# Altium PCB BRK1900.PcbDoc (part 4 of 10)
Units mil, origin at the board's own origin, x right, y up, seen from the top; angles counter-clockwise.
Board outline 8858.27 x 5905.51 mil, 10 copper layers (L1-TOP, L2-GND, L3-SIG1, L4-GND, L5-PWR, L6-PWR, L7-GND, L8-SIG2, L9-GND, L10-BOT), stack 48.824 mil thick; 507 components, 607 nets, 2498 pads, 2210 vias.
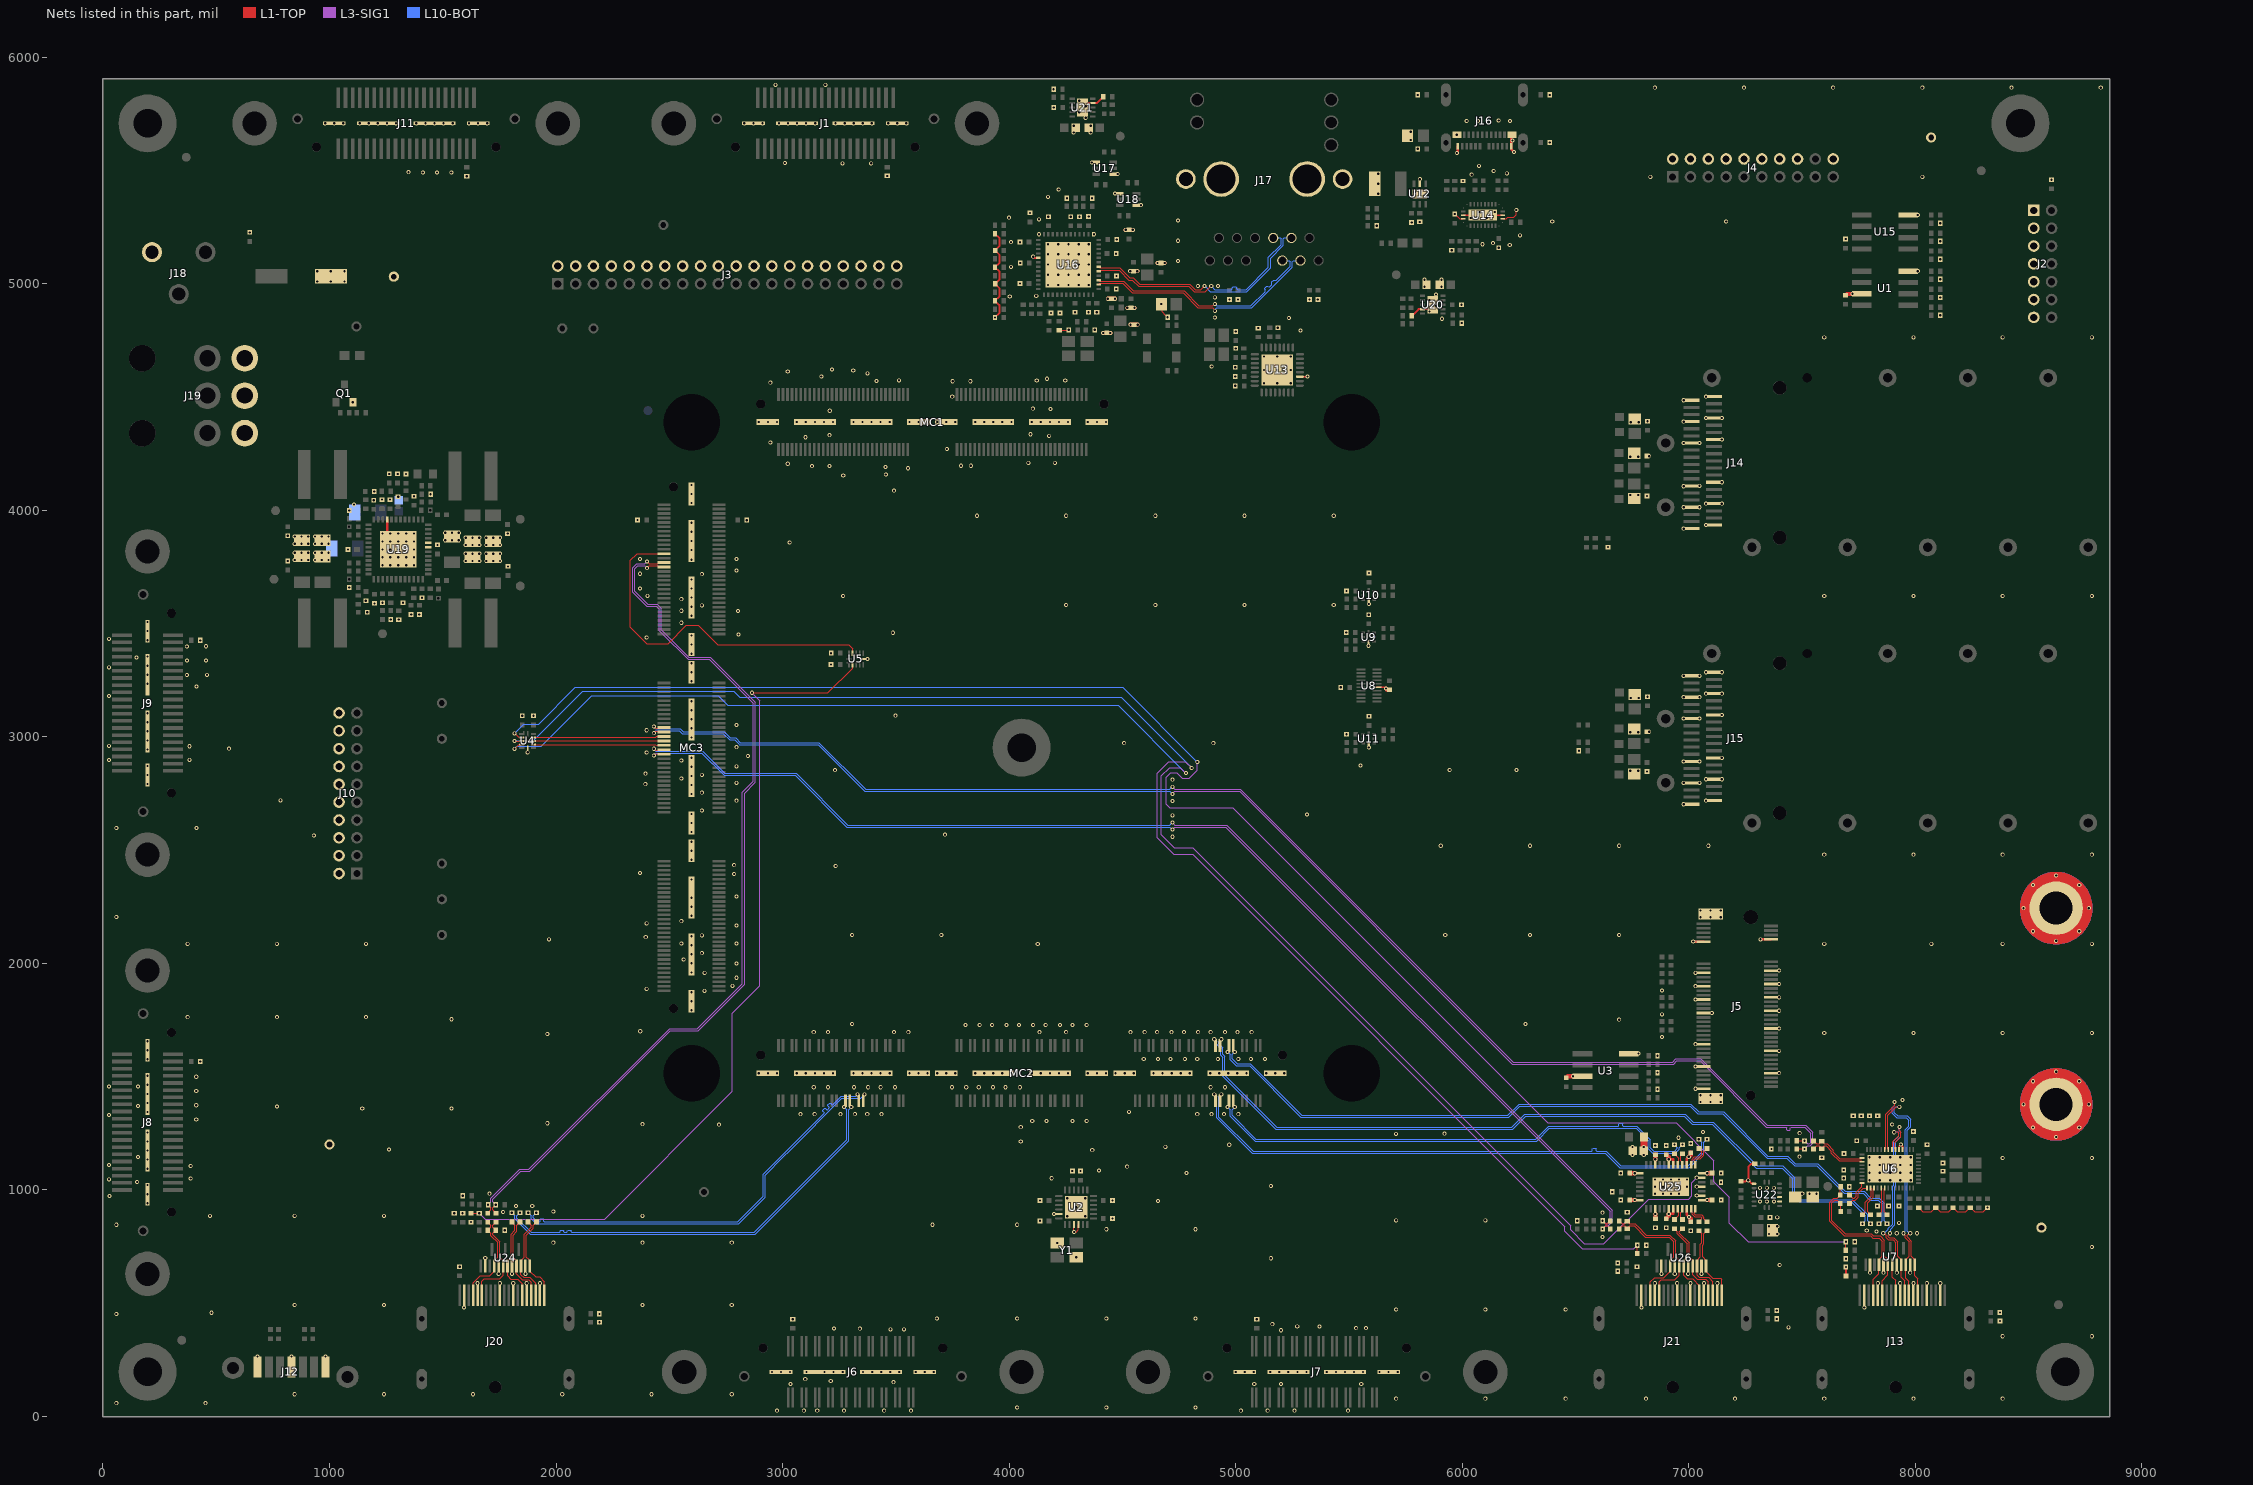
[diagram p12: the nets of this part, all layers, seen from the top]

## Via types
v1: diameter 18, hole 10, L1-TOP to L10-BOT, tented both sides, 2210 vias

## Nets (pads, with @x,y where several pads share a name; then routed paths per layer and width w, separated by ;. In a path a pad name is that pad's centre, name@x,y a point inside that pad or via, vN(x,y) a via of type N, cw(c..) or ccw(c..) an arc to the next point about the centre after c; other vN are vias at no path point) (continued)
DGND: C1.1 C2.1 C3.1 C4.1 C5.1 C6.1 C7.1 C8.1 C9.1 C18.1 C19.1 C20.2 C21.2 C22.1 C23.1 C29.1 C37.1 C38.2 C39.2 C40.1 C41.1 C42.1 C43.1 C44.1 C45.1 C46.1 C47.1 C48.1 C49.1 C50.1 C51.1 C52.1 C53.1 C54.1 C55.1 C56.1 C57.1 C58.1 C59.1 C60.1 C61.1 C62.1 C63.1 C64.1 C65.1 C66.1 C67.1 C68.1 C69.1 C70.1 C71.1 C72.1 C73.1 C74.1 C75.1 C76.1 C77.1 C78.1 C81.1 C82.1 C83.1 C84.1 C85.2 C86.1 C87.2 C88.1 C89.1 C90.1 C91.1 C92.1 C93.1 C94.1 C95.1 C96.2 C97.1 C98.1 C99.1 C100.1 C101.2 C102.1 C103.2 C104.1 C105.1 C106.1 C107.1 C108.1 C109.1 C110.2 C111.2 C112.1 C113.1 C114.1 C115.1 C116.2 C117.2 C119.1 C120.1 C121.1 C123.2 C124.2 C125.2 C127.2 C128.2 C129.1 C130.1 C131.1 C132.1 C134.2 C135.1 C136.2 C137.2 C138.2 C140.2 C141.2 C142.1 C143.1 C144.1 C146.2 C147.2 C148.2 C150.1 C151.1 C152.1 C155.2 C156.1 C157.2 C158.1 C159.1 C160.1 C162.1 C164.1 C165.1 C167.1 C168.1 C169.1 C176.1 C177.1 C183.1 C190.1 C191.1 C192.1 C193.1 C194.1 C195.1 C196.1 C197.1 C198.1 C199.1 C200.1 C201.1 C204.1 C211.1 FB1.2 J1.0 J2.1 J2.3 J2.5 J2.7 J2.9 J2.11 J2.13 J3.2 J3.4 J3.6 J3.8 J3.10 J3.12 J3.14 J3.16 J3.18 J3.20 J3.22 J3.24 J3.26 J3.28 J3.30 J3.32 J3.34 J3.36 J3.38 J3.40 J4.2 J4.4 J4.6 J4.8 J4.10 J4.12 J4.14 J4.16 J4.20 J5.1 J5.8 J5.11 J5.18 J5.21 J5.28 J5.35 J5.36 J5.41 J5.42 J5.47 J5.48 J5.53 J5.54 J5.67 J5.68 J6.0 J7.0 J8.0 J9.0 J10.2 J10.4 J10.6 J10.8 J10.10 J10.12 J10.14 J10.16 J10.18 J10.20 J11.0 J12.1 J12.4 J12.7 J13.2 J13.5 J13.8 J13.11 J13.16 J13.19 J14.1 J14.4 J14.7 J14.13 J14.16 J14.19 J14.20 J14.23 J14.26 J14.32 J14.35 J14.38 J15.1 J15.4 J15.7 J15.13 J15.16 J15.19 J15.20 J15.23 J15.26 J15.32 J15.35 J15.38 J16.A1 J16.A12 J16.B1 J16.B12 J17.S1 J17.S2 J17.T1 J17.T2 J18.2 J19.4 J19.5 J19.6 J20.2 J20.5 J20.8 J20.11 J20.16 J20.19 J21.2 J21.5 J21.8 J21.11 J21.16 J21.19 MC1.0 MC2.0 MC3.0 Q1.2 R1.1 R5.1 R6.1 R7.1 R11.1 R12.1 R13.1 R14.1 R15.1 R16.1 R17.1 R18.1 R19.2 R20.2 R21.2 R22.2 R25.1 R26.1 R27.1 R28.1 R29.1 R35.1 R36.1 R37.1 R38.1 R39.1 R40.1 R47.1 R60.1 R66.1 R70.2 R73.2 R76.1 R77.2 R78.2 R79.2 R83.1 R87.1 R88.1 R89.1 R98.1 R99.1 R100.1 R101.1 R102.1 R103.1 R109.2 R114.1 R115.1 R116.1 R119.1 R123.1 R126.1 R130.1 R131.2 R134.1 R135.1 R142.1 R143.1 R147.1 R150.2 R151.2 R154.1 R155.1 R156.1 R157.1 R159.1 R161.1 R162.1 R163.1 R164.1 R165.1 R166.1 R169.1 R171.1 R175.1 R177.1 SO1.1 SO2.1 TP2.1 TP5.1 TP8.1 TP11.1 U1.4 U1.7 U2.3 U2.4 U2.23 U2.PAD U3.4 U3.7 U4.6 U5.6 U6.13 U6.14 U6.PAD U7.2 U7.5 U7.8 U7.11 U8.15 U9.4 U10.4 U11.4 U12.0 U12.5 U13.0 U13.11 U14.12 U14.13 U14.28 U14.29 U14.PAD U15.4 U16.0 U16.13 U16.29 U17.1 U17.4 U18.1 U18.4 U19.7 U19.8 U19.21 U19.PAD U20.4 U20.PAD U21.4 U21.PAD U22.2 U22.3 U22.9 U24.2 U24.5 U24.8 U24.11 U25.33 U25.35 U25.PAD U26.2 U26.5 U26.8 U26.11 Y1.2 Y1.4 | length 5920.7
  L1-TOP w5: R114.1@4222.06,4795.45 4261.3,4795.45 v1(4262.98,4797.14) ; U2.3@4286.39,847.02 4286.39,815.08 v1(4287.13,814.34) 4296.78,814.34 4306.07,823.63 U2.4@4306.07,847.02 ; v1(4671.82,4910.57) 4675.7,4906.7 4675.7,4876.48 4690.29,4861.89 4692.26,4861.89 4699.6,4854.54 v1(4699.6,4852.57) ; v1(5967.41,5308.4) 5968,5308.4 5975.74,5300.67 5975.74,5300.07 5988.31,5287.5 U14.29@6005.76,5287.5 ; U14.12@6178.99,5287.5 6194.5,5287.5 6201,5294 6227.22,5294 6239.22,5306 v1(6239.22,5326) ; R36.1@8014.77,922.57 8034.09,903.26 8071.46,903.26 R37.1@8090.77,922.57 8110.09,903.26 8147.46,903.26 R38.1@8166.77,922.57 8186.09,903.26 8223.46,903.26 R39.1@8242.77,922.57 8262.09,903.26 8299.46,903.26 v1(8318.77,922.57)
  L1-TOP w7: U13.11@5283.35,4590.53 5317.07,4590.53 v1(5317.41,4590.87) ; v1(7693.84,660) 7694.45,659.39 C29.1@7694.45,621 ; U6.14@7928.5,1179.26 7928.5,1193.25 v1(7936.34,1201.08) 7944.25,1193.17 U6.13@7944.25,1179.26
  L1-TOP w7.5: U8.15@5623.43,3219.13 5657.74,3219.13 v1(5663.37,3213.5) ; U14.28@6005.76,5303.24 6091,5303.24 U14.PAD@6091.59,5303.83 6092.18,5303.24 U14.13@6178.99,5303.24
  L1-TOP w8: v1(3937.8,4851.42) 3957,4870.62 3957,4906.22 R98.1@3937.8,4925.42 3958,4945.62 3958,4979.62 R103.1@3937.94,4999.68 3958,5019.73 3958,5053.12 R102.1@3937.7,5073.41 3958,5093.71 3958,5127.3 R101.1@3937.89,5147.41 3958,5167.53 3958,5201.22 R100.1@3937.8,5221.42
  L1-TOP w9: v1(4106.06,5120.14) 4111.39,5114.81 U16.29@4128.04,5114.81 ; U21.PAD@4323.94,5778.23 4343.62,5797.91 U21.4@4369.21,5797.91 4386.46,5797.91 4415,5826.46 R143.1@4416.31,5826.46 ; R142.1@5777.62,4859.77 5778.94,4859.77 5807.48,4888.31 U20.4@5824.72,4888.31 5850.31,4888.31 U20.PAD@5870,4908 ; C177.1@7235,1036.59 7250.11,1036.59 7256,1042.48 v1(7263,1042.48) ; U22.9@7285.94,1027.69 7278.79,1027.69 7264,1042.48 v1(7263,1042.48) ; R147.1@7291,1114.2 7274.72,1114.2 7263,1102.48 v1(7263,1042.48)
  L1-TOP w11: C157.2@1158.5,3601.56 C157.2@1161.58,3601.56 ; C146.2@1197.7,3589.45 v1(1198.29,3589.45) ; U19.21@1254.37,3959.53 1254.37,3876.85 v1(1303.58,3827.64) ; C156.1@1269.81,3518.08 v1(1270.4,3518.08) ; R134.1@1304.81,3517.87 v1(1305.4,3517.87) ; C124.2@1324.41,3591.92 v1(1325,3591.92) ; C125.2@1359.99,3540.48 v1(1360.58,3540.48) ; v1(5976.48,5578.02) 5980.31,5581.85 J16.A12@5980.31,5607.09 ; J16.A1@6216.17,5602.2 6216.17,5594.75 v1(6228.82,5582.1) ; J16.A1@6216.54,5607.09 6216.54,5654.33 J16.B12@6220.47,5658.27 ; v1(7019.94,2096.46) J5.67@7065.94,2096.46 ; v1(7317.19,2106.3) J5.68@7363.19,2106.3
  L1-TOP w18: v1(4415.25,4783.49) C96.2@4431,4783.49 v1(4446.75,4783.49) ; v1(4435.86,4934.37) C85.2@4451.61,4934.37 v1(4467.35,4934.37) ; v1(4514.65,5238.47) v1(4546.14,5238.47) C101.2@4530,5238.47 ; v1(4521.86,4894.21) C86.1@4537.61,4894.21 v1(4553.35,4894.21) ; v1(4534.27,5055.99) C103.2@4550.02,5055.99 v1(4565.76,5055.99) ; v1(4536.25,4819.65) C95.1@4552,4819.65 v1(4567.75,4819.65) ; v1(4655.27,5092.15) C102.1@4671.02,5092.15 v1(4686.76,5092.15) ; v1(5663.37,3213.5) 5669.29,3207.58 C56.1@5678.63,3207.58 ; C9.1@6459.6,1496.23 6460.19,1496.23 6466.11,1502.15 v1(6489.24,1502.15) U3.7@6531.24,1502.15 ; C2.1@7693,4950.08 7693.59,4950.08 7699.51,4956 v1(7722.64,4956) U1.7@7764.64,4956 ; C94.1@7693,5198.08 C94.1@7693.59,5198.08
  L1-TOP w60: 8752.05,1377.95 ccw(c8622.05,1377.95) 8752.05,1377.95 ; 8752.05,2244.09 ccw(c8622.05,2244.09) 8752.05,2244.09
  L10-BOT w7: v1@1233.58,3754.66 v1(1233.58,3757.64)
  L10-BOT w60: 8752.05,1377.95 ccw(c8622.05,1377.95) 8752.05,1377.95 ; 8752.05,2244.09 ccw(c8622.05,2244.09) 8752.05,2244.09
  other v1: 2975.93,25.8 3094.04,25.8 3153.1,25.8 3271.21,25.8 3448.38,25.8 3566.49,25.8 5023.18,25.8 5141.29,25.8 5259.4,25.8 5495.62,25.8 4035.43,39.37 4429.13,39.37 4822.83,39.37 59.06,59.06 452.76,59.06 5708.66,78.74 6102.36,78.74 6456.69,78.74 6811.02,78.74 7204.72,78.74 7598.43,78.74 7992.13,78.74 8385.83,78.74 846.46,98.43 1240.16,98.43 1633.86,98.43 2027.56,98.43 2421.26,98.43 2775.59,98.43 3034.99,143.91 5082.23,143.91 5200.34,143.91 5554.67,143.91 3489.31,151.62 3212.85,156.8 3100,165 2952.88,196.85 2992.88,196.85 3032.88,196.85 3105.38,196.85 3185.38,196.85 3225.38,196.85 3265.38,196.85 3355.38,196.85 3395.38,196.85 3435.38,196.85 3475.38,196.85 3515.38,196.85 3587.88,196.85 3627.88,196.85 3667.88,196.85 5000.13,196.85 5040.13,196.85 5080.13,196.85 5152.63,196.85 5192.63,196.85 5232.63,196.85 5272.63,196.85 5312.63,196.85 5402.63,196.85 5442.63,196.85 5482.63,196.85 5522.63,196.85 5562.63,196.85 5635.13,196.85 5675.13,196.85 5715.13,196.85 682.48,265.5 832.48,265.5 982.48,265.5 8385.83,354.33 8779.53,354.33 5200,381 3477,385 3536,385 3226.85,388.35 3341,388 5532,390 5576,390 7440.94,393.7 5370,397 5272,398 5162.11,407.59 2192.08,416 8374.08,422 3045,429.69 5093,429.69 7388.69,431 3681.1,433.07 4035.43,433.07 4429.13,433.07 4822.83,433.07 59.06,452.76 2191.69,453 479.55,457.99 8373.69,459 7389.08,468 5708.66,472.44 6102.36,472.44 6456.69,472.44 1594.28,480.95 6791.13,480.95 7775.38,480.95 846.46,492.13 1240.16,492.13 2381.89,492.13 2775.59,492.13 1653.75,588.34 1752.18,588.34 1811.23,588.34 1870.29,588.34 1929.34,588.34 6850.6,588.34 6949.03,588.34 7008.08,588.34 7067.14,588.34 7126.19,588.34 7834.85,588.34 7933.28,588.34 7992.33,588.34 8051.39,588.34 8110.44,588.34 1746.72,629.96 1805.78,629.96 1864.83,629.96 6879.4,629.81 6938.46,629.81 6997.51,629.81 7056.57,629.81 7800.59,634.96 7859.65,634.96 7918.7,634.96 7977.76,634.96 6686.84,642 1574.53,661.08 6771.53,661.08 7401.57,669.29 6686.84,678 7693.84,697 5155.54,698.66 1687.67,700.04 4295.96,703.29 8779.53,748.03 6813.21,756 4212.5,766.28 1988.19,767.72 2381.89,767.72 2775.59,767.72 7733.21,771 6619.69,792 7354,805.32 7390.84,805.32 7918.44,809 8007.72,809 7828.94,816.27 7009,819.92 7786,821 1773.9,822 4429.13,826.77 4822.83,826.77 6852.83,833.36 6900.83,833.36 7354,839.48 7390.84,839.48 59.06,846.46 3661.42,846.46 4035.43,846.46 7928,855 1624.53,858.31 4136.15,863.79 6508.31,864 5708.66,866.14 6102.36,866.14 4456.31,873.79 7359.08,879.48 7390.84,879.19 4256.23,883.79 4336.23,883.79 472.44,885.83 846.46,885.83 1240.16,885.83 2381.89,885.83 4198.46,894.26 1550.53,897.69 1587.53,897.69 6619.68,900 6729,901.37 1766.53,903 1988.19,905.51 4296.23,923.79 1823.09,929.08 1895.09,929.08 7832.77,929.18 7882.77,929.18 7928.77,929.18 196.85,941.71 7315,949.48 7345,949.48 7377,949.48 4657.81,951.76 4136.15,953.79 4456.31,953.79 6699.75,955.44 7142.91,955.44 4256.23,963.79 4336.23,963.79 28.71,973.62 1588.84,975 7035.43,975.51 196.85,981.71 6850.75,983.39 6886.18,983.39 6921.61,983.39 6957.05,983.39 1706.53,984 7501.18,983.94 7533.52,983.94 7564.17,983.94 6662.2,991.59 7315,1009.48 7345,1009.48 7376,1009.48 7709.69,1014 6850.75,1014.88 6886.18,1014.88 6921.61,1014.88 6957.05,1014.88 6992.48,1014.88 7035.43,1014.88 5155.48,1017.28 196.85,1021.71 7142.51,1034.44 151,1035 7798.58,1042.84 7843.86,1042.84 7889.13,1042.84 7934.41,1042.84 7979.68,1042.84 6850.75,1046.38 6886.18,1046.38 6921.61,1046.38 6957.05,1046.38 6992.48,1046.38 27.05,1047.26 387.02,1050.31 4188,1051.75 7684.69,1052.26 6699.75,1074.44 7142.91,1074.44 4782.62,1074.91 7798.58,1076.7 7843.86,1076.7 7889.13,1076.7 7934.41,1076.7 7979.68,1076.7 8121.77,1083.42 4279.23,1083.87 4315.23,1083.87 4397,1085.75 7684.69,1088.26 196.85,1094.21 4521.04,1102.89 387.2,1106.15 27.05,1110.26 7798.58,1110.56 7843.86,1110.56 7889.13,1110.56 7934.41,1110.56 7979.68,1110.56 8121.77,1119.1 196.85,1134.21 8385.83,1141.73 8779.53,1141.73 7587,1143.31 7798.58,1144.42 7843.86,1144.42 7889.13,1144.42 7934.41,1144.42 7979.68,1144.42 155,1146 7489,1147 6752.22,1154.72 7685.69,1160.26 196.85,1174.21 4367.19,1175.79 1263.13,1178.3 7365.31,1181 6752.22,1190.16 4689.61,1190.54 6852.83,1196.52 6900.83,1196.52 4971.95,1199.76 8052.77,1200.34 7009,1205.08 196.85,1214.21 4051.5,1214.25 7741.69,1217.26 6954.83,1230.52 8622.05,1233.61 5707.77,1247.95 5921.49,1248.55 7490,1251 196.85,1254.21 7063,1256 7991.77,1258.42 8519.98,1275.89 8724.11,1275.89 4051.5,1277.24 2719.41,1288.53 7898.33,1289.21 2381.35,1290.51 1961.7,1294.62 4102.36,1304.6 4165.35,1304.6 4279.53,1304.6 4342.52,1304.6 412.01,1311.07 7725.77,1326.94 7761.77,1326.94 7797.77,1326.94 7833.77,1326.94 27.05,1330.76 3078.74,1334.6 3141.73,1334.6 3255.91,1334.6 3318.9,1334.6 3374.02,1334.6 3437.01,1334.6 4830.71,1334.6 4893.7,1334.6 4948.82,1334.6 5011.81,1334.6 196.85,1344.21 4529.39,1344.86 1144.64,1359.87 1538.35,1359.87 767.84,1369.07 155,1371 412.01,1374.07 8477.71,1377.95 8766.39,1377.95 196.85,1384.21 7052,1388.09 7096.46,1388.09 7140.91,1388.09 7943.6,1397.68 7052,1418 7096.46,1418 7140.91,1418 196.85,1424.21 412.01,1437.07 6862.28,1444.15 7029.94,1446.85 3137.8,1453.59 3200.79,1453.59 3314.96,1453.59 3377.95,1453.59 3433.07,1453.59 3496.06,1453.59 3748.03,1453.59 3811.02,1453.59 3866.14,1453.59 3929.13,1453.59 3984.25,1453.59 4047.24,1453.59 4889.76,1453.59 4952.76,1453.59 27.05,1456.76 154.35,1456.76 196.85,1464.21 8519.98,1480.02 8724.11,1480.02 412.01,1500.07 196.85,1504.21 2895.24,1515.75 2935.24,1515.75 2975.24,1515.75 3062.72,1515.75 3102.72,1515.75 3142.72,1515.75 3182.72,1515.75 3222.72,1515.75 3312.72,1515.75 3352.72,1515.75 3392.72,1515.75 3432.72,1515.75 3472.72,1515.75 3560.2,1515.75 3600.2,1515.75 3640.2,1515.75 3682.64,1515.75 3722.64,1515.75 3762.64,1515.75 3850.12,1515.75 3890.12,1515.75 3930.12,1515.75 3970.12,1515.75 4010.12,1515.75 4100.12,1515.75 4140.12,1515.75 4180.12,1515.75 4220.12,1515.75 4260.12,1515.75 4347.6,1515.75 4387.6,1515.75 4427.6,1515.75 4470.04,1515.75 4510.04,1515.75 4550.04,1515.75 4637.52,1515.75 4677.52,1515.75 4717.52,1515.75 4757.52,1515.75 4797.52,1515.75 4887.52,1515.75 4927.52,1515.75 4967.52,1515.75 5007.52,1515.75 5047.52,1515.75 5135,1515.75 5175,1515.75 5215,1515.75 7399.19,1515.75 6862.28,1518.15 8622.05,1522.29 7029.94,1545.28 429.69,1567 196.85,1576.71 4594.49,1577.91 4657.48,1577.91 4712.6,1577.91 4775.59,1577.91 4830.71,1577.91 4921.26,1577.91 5011.81,1577.91 5066.93,1577.91 5129.92,1577.91 6862.28,1592.15 6777.96,1602.15 7399.19,1614.17 196.85,1616.71 7029.94,1643.7 196.85,1656.71 6881.92,1675.51 1961.7,1688.32 7598.43,1692.91 7992.13,1692.91 8385.83,1692.91 8779.53,1692.91 3137.8,1696.9 3200.79,1696.9 3492.13,1696.9 3555.12,1696.9 4133.86,1696.9 4251.97,1696.9 4535.43,1696.9 4598.42,1696.9 4653.54,1696.9 4716.54,1696.9 4771.65,1696.9 4834.65,1696.9 4889.76,1696.9 4952.76,1696.9 5007.87,1696.9 5070.87,1696.9 2371.64,1700.6 7399.19,1712.6 3807.09,1728.39 3870.08,1728.39 3925.2,1728.39 3988.19,1728.39 4043.31,1728.39 4106.3,1728.39 4161.42,1728.39 4224.41,1728.39 4279.53,1728.39 4342.52,1728.39 3307.09,1732.28 6279.53,1732.28 6692.91,1751.97 1538.35,1753.57 374.14,1762.77 767.84,1762.77 1161.54,1762.77 6881.92,1775.5 7101.94,1781.5 7399.19,1791.34 2598.42,1792.87 2598.42,1832.87 7029.94,1840.55 7399.19,1850.39 2598.42,1872.87 2655.37,1879.15 6881.92,1881 2400.28,1887.8 7029.94,1899.61 2778.67,1901.21 7399.19,1909.45 2796.57,1936.88 2656.13,1958.52 7029.94,1958.66 2598.42,1960.35 7399.19,1968.5 2598.42,2000.35 2796.57,2000.03 2563.64,2017.68 2598.42,2040.35 2643.58,2045.28 2598.42,2080.35 4126.55,2085.79 374.02,2086.61 767.72,2086.61 1161.42,2086.61 7598.43,2086.61 8070.87,2086.61 8385.83,2086.61 8779.53,2086.61 2553.27,2088.48 2796.57,2088.58 8622.05,2099.76 1968.5,2106.3 2396,2116 2598.42,2120.35 2643.58,2124.02 3307.09,2125.98 3700.79,2125.98 5925.2,2125.98 6299.21,2125.98 6692.91,2125.98 8519.98,2142.03 8724.11,2142.03 2796.57,2167.32 2400.28,2177.2 2553.27,2186.91 7052,2204.05 7096.46,2204.05 7140.91,2204.05 59.06,2204.72 2598.42,2210.35 7052,2233.96 7096.46,2233.96 7140.91,2233.96 8477.71,2244.09 8766.39,2244.09 2598.42,2250.35 2598.42,2290.35 2796.44,2295.95 8519.98,2346.16 8724.11,2346.16 2598.42,2370.35 8622.05,2388.43 2786.57,2394.67 2370.28,2399.61 3234.54,2430.29 2786.57,2434.04 2598.42,2457.83 7598.43,2480.32 7992.13,2480.32 8385.83,2480.32 8779.53,2480.32 2598.42,2497.83 5905.51,2519.68 6299.21,2519.68 6692.91,2519.68 7086.61,2519.68 2598.42,2537.83 4721,2559.37 931,2565 3716.72,2568.55 2598.42,2580.28 59.06,2598.43 413.39,2598.43 2598.42,2620.28 4721,2653.86 5314.96,2657.48 2598.42,2660.28 2643.58,2675.2 6977.61,2702.92 4721,2716.85 2796.57,2718.5 7076.43,2718.67 784,2720 2598.42,2747.76 2643.58,2753.94 2598.42,2787.76 2394.28,2791.31 196.85,2792.11 2796.57,2797.24 6977.61,2797.41 7047.61,2797.41 4721,2811.34 7076.43,2813.16 7146.43,2813.16 2553.27,2816.93 2598.42,2827.76 196.85,2832.11 2643.58,2832.68 2394.85,2837.88 6815.79,2847.17 6741.79,2851.24 6777.79,2851.24 3231.05,2853.21 5944.88,2854.33 6240.16,2854.33 2598.42,2867.76 2796.85,2870.17 196.85,2872.11 5551.18,2874.02 6977.61,2891.9 7047.61,2891.9 2553.27,2895.67 27.05,2897.66 381.68,2899.01 2598.42,2907.76 7146.43,2907.65 2846.57,2915.35 2400.28,2931.1 1875,2932 6515.31,2938.7 196.85,2944.61 556,2948 5588,2953.36 2796.57,2954.72 381.62,2958.8 27.05,2960.66 4507.87,2972.44 4901.57,2972.44 196.85,2984.61 2598.42,2997.76 5489.38,3011.65 6741.79,3020.24 6777.79,3020.24 6825.64,3022.77 196.85,3024.61 2400.28,3029.53 2598.42,3037.76 2796.57,3053.15 196.85,3064.61 2598.42,3077.76 6977.61,3080.87 7047.61,3080.87 5588.46,3090.72 1851,3093.08 1901,3093.08 3498.28,3093.72 7146.43,3096.62 196.85,3104.61 2598.42,3117.76 2598.42,3157.76 6744,3172.18 6780,3172.18 6977.61,3175.36 7047.61,3175.36 6817.81,3177.26 27.05,3181.16 7076.43,3191.11 7146.43,3191.11 5463.92,3219 413.36,3223.05 196.85,3234.61 2598.42,3245.24 6977.61,3269.85 7047.61,3269.85 370.31,3273.85 459.14,3274 196.85,3274.61 2598.42,3285.24 7076.43,3285.6 7146.43,3285.6 27.05,3307.16 196.85,3314.61 3214.09,3320.17 2598.42,3325.24 370.6,3337.19 454.75,3336.87 3375,3344 147.79,3351.01 196.85,3354.61 2598.42,3367.68 3214.3,3369.62 370.48,3398.93 455.2,3400.18 5587,3402.36 2598.42,3407.68 429.69,3426 196.85,3427.11 27.05,3433.16 2400.28,3438.98 2598.42,3447.68 2805.07,3452.56 3486.66,3459.72 5488.38,3460.65 196.85,3467.11 2553.27,3503.94 196.85,3507.11 2598.42,3535.16 5587.46,3539.72 1396.66,3540.56 1166.24,3550.66 2802.87,3556.33 2553.27,3557.09 2598.42,3575.16 2643.58,3580.71 4251.97,3582.68 4645.67,3582.68 5039.37,3582.68 5433.07,3582.68 5588,3586.36 1234.29,3591.84 1160.04,3601.56 2553.27,3608.27 1408.58,3613.95 2598.42,3615.16 3267.72,3622.05 7598.43,3622.05 7992.13,3622.05 8385.83,3622.05 8779.53,3622.05 2404,3623 5489.38,3644.65 2598.42,3655.16 2370.28,3655.51 1087.21,3659.64 2598.42,3695.16 2643.58,3718.5 2370.28,3720.47 5588.46,3723.72 2796.57,3734.25 1787.58,3752.72 1268.58,3757.64 1303.58,3757.64 1338.58,3757.64 1373.58,3757.64 815.58,3776.8 1601.58,3776.64 1631.58,3776.64 1661.58,3776.64 1692.58,3776.64 1722.58,3776.64 1752.58,3776.64 846.18,3780.64 876.18,3780.64 905.88,3780.64 935.58,3780.64 965.58,3780.64 995.58,3780.64 2597.63,3781.99 2370.28,3785.43 2796.57,3785.43 1233.58,3792.64 1268.58,3792.64 1303.58,3792.64 1338.58,3792.64 1373.58,3792.64 1601.58,3808.81 1631.58,3808.81 1661.58,3808.81 1692.58,3808.81 1722.58,3808.81 1752.58,3808.81 846.18,3812.81 876.18,3812.81 905.88,3812.81 935.58,3812.81 965.58,3812.81 995.58,3812.81 2598.42,3825.16 1081.5,3827.64 1233.58,3827.64 1268.58,3827.64 1338.58,3827.64 1373.58,3827.64 6644,3838.02 1601.58,3847.46 1631.58,3847.46 1661.58,3847.46 1692.58,3847.46 1722.58,3847.46 1752.58,3847.46 1476.58,3847.72 846.18,3852.46 876.18,3852.46 905.88,3852.46 935.58,3852.46 965.58,3852.46 995.58,3852.46 3031.5,3858.27 1233.58,3862.64 1268.58,3862.64 1303.58,3862.64 1338.58,3862.64 1373.58,3862.64 2598.42,3865.16 1510.58,3868.64 1540.58,3868.64 1570.58,3868.64 1601.58,3879.64 1631.58,3879.64 1661.58,3879.64 1692.58,3879.64 1722.58,3879.64 1752.58,3879.64 846.18,3884.64 876.18,3884.64 905.88,3884.64 935.58,3884.64 965.58,3884.64 995.58,3884.64 815.58,3887.56 1233.58,3897.64 1268.58,3897.64 1303.58,3897.64 1338.58,3897.64 1373.58,3897.64 1786.58,3897.56 1510.58,3900.81 1540.58,3900.81 1570.58,3900.81 2598.42,3905.16 6977.61,3919.39 7076.43,3935.14 2598.42,3945.16 2842.16,3957 2359.92,3958 3858.27,3976.38 4251.97,3976.38 4645.67,3976.38 5039.37,3976.38 5433.07,3976.38 1086.9,3999.64 6977.61,4013.88 7047.61,4013.88 1108.58,4025.64 7076.43,4029.63 7146.43,4029.63 2598.42,4032.64 1195.29,4044.61 1231.58,4047.72 1267.58,4047.72 1303.58,4059.72 1372.58,4062.8 6815.8,4063.64 6741.8,4067.72 6777.8,4067.72 1446.27,4071.64 2598.42,4072.64 1197.66,4083.64 3492,4087 6977.62,4106.48 7047.61,4108.37 2598.42,4112.06 7146.43,4124.12 3268,4154 3456,4158 1264,4161.08 1301,4161.08 1337.58,4160.72 3554,4186 3454,4192 3130.21,4195.27 3207.01,4196.45 3788,4197 3831,4197 3023,4206 4085,4210 4202,4210 6741.8,4236.72 6777.8,4236.72 6825.65,4239.24 3725,4271 6977.61,4297.35 7047.61,4297.35 2946,4300 7146.43,4313.09 3101,4323 4176.89,4329.26 3207,4332 4095,4336 6744.01,4388.65 6780.01,4388.65 2895.24,4389.76 2935.24,4389.76 2975.24,4389.76 3062.72,4389.76 3102.72,4389.76 3142.72,4389.76 3182.72,4389.76 3222.72,4389.76 3312.72,4389.76 3352.72,4389.76 3392.72,4389.76 3432.72,4389.76 3472.72,4389.76 3560.2,4389.76 3600.2,4389.76 3640.2,4389.76 3682.64,4389.76 3722.64,4389.76 3762.64,4389.76 3850.12,4389.76 3890.12,4389.76 3930.12,4389.76 3970.12,4389.76 4010.12,4389.76 4100.12,4389.76 4140.12,4389.76 4180.12,4389.76 4220.12,4389.76 4260.12,4389.76 4347.6,4389.76 4387.6,4389.76 4427.6,4389.76 6977.61,4391.83 6817.81,4393.73 7076.43,4407.58 7146.43,4407.58 3208.32,4439.68 4183,4448 4105,4449 1103.1,4477.3 6977.61,4486.32 3749,4502 7076.43,4502.07 4998.33,4549.87 5124.89,4561 5183.94,4561 5243,4561 2946,4564 3751,4570 3829,4570 3415,4571 4122,4573 4248,4573 3514,4574 4167,4581 3171,4591 4998.33,4590.87 3375,4605 3023,4613 3312,4617 5124.89,4620.06 5183.94,4620.06 5243,4620.06 3218,4622 4998.33,4631.87 4894,4634.75 5124.89,4679.11 5183.94,4679.11 5243,4679.11 5000.41,4714.95 7598.43,4763.78 7992.13,4763.78 8385.83,4763.78 8779.53,4763.78 5000.41,4789.95 5286.76,4793.71 4378.14,4797.14 5100,4804.69 5186.41,4805.95 5997.62,4826.77 5911,4846 5235,4849 4908,4851.05 8110.69,4861 4185.06,4871.06 4225.06,4871.06 4291.06,4874.06 4350.06,4874.06 4387.06,4874.77 5855.94,4877.77 5884.06,4902.77 5997.04,4907.56 5855.94,4928.23 4973,4930.92 5010,4930.92 5326,4930.92 5363,4930.92 4908,4940.32 8110.69,4940 4003,4944 4120,4947 5884.06,4953.23 4473.22,4977.14 5833.94,4987.77 5908.94,4987.77 4833,4991 4922.28,4991 4171.9,4995.28 4216.9,4995.28 4261.9,4995.28 4306.9,4995.28 4351.9,4995.28 4047.98,5001.14 945.91,5010 1005.91,5010 1065.91,5010 5833.94,5018.3 5908.94,5018.3 8110.69,5020 4474.22,5035.14 4171.9,5040.28 4216.9,5040.28 4261.9,5040.28 4306.9,5040.28 4351.9,5040.28 945.91,5056 1005.91,5056 1065.91,5056 8011.36,5056 4008,5075 4171.9,5085.28 4216.9,5085.28 4261.9,5085.28 4306.9,5085.28 4351.9,5085.28 4048.98,5092.14 4746,5101.05 8110.69,5109 4171.9,5130.28 4216.9,5130.28 4261.9,5130.28 4306.9,5130.28 4351.9,5130.28 4472.22,5133.14 5954.41,5148.64 6161.35,5159.92 6210,5172 4171.9,5175.28 4216.9,5175.28 4261.9,5175.28 4306.9,5175.28 4351.9,5175.28 6089.36,5174.88 6136.01,5179.65 4008,5184 4047.98,5184.14 8110.69,5188 4746,5190.32 4475.22,5196.14 7693.3,5198.08 6255,5214 4132.18,5218.96 4374.98,5218.91 648,5227.08 5622.69,5257 8110.69,5268 5777.06,5270.88 5813.06,5273.28 6397.64,5275.59 7165.35,5275.59 4746,5279.6 4132,5285 6038.41,5290.32 6108.41,5290.32 4000,5292 4173.06,5296.22 4272.06,5296.22 4311.06,5296.22 4351.06,5297.3 8011.36,5304 4092,5313.08 6075.41,5317.32 6143.41,5317.32 4582,5347.41 4255.37,5378.14 4366.43,5378.14 4172,5384 5835.06,5386.96 5629.89,5397.96 4468,5398.59 5791.06,5406.96 4219,5416 5629.89,5441.96 6003.41,5454.01 8602,5460.08 5813.06,5461.96 6830.71,5472.44 8031.5,5472.44 1606,5475.31 3462,5476.31 6042,5482 4479.23,5484.41 5629.89,5485.96 6197,5488 1412,5492 1475,5492 1538,5492 1349,5493 6139,5498 6074,5521 3265,5532 3391,5532 3010,5533 4365.23,5535.59 5803.92,5596 6386.69,5624 6222.48,5633.1 5773,5635 5976.38,5658.27 4285,5667.93 4360,5667.93 5773,5671 4285,5698.46 4360,5698.46 981.08,5708.66 1021.08,5708.66 1061.08,5708.66 1133.58,5708.66 1173.58,5708.66 1213.58,5708.66 1253.58,5708.66 1293.58,5708.66 1383.58,5708.66 1423.58,5708.66 1463.58,5708.66 1503.58,5708.66 1543.58,5708.66 1616.08,5708.66 1656.08,5708.66 1696.08,5708.66 2831.48,5708.66 2871.48,5708.66 2911.48,5708.66 2983.98,5708.66 3023.98,5708.66 3063.98,5708.66 3103.98,5708.66 3143.98,5708.66 3233.98,5708.66 3273.98,5708.66 3313.98,5708.66 3353.98,5708.66 3393.98,5708.66 3466.48,5708.66 3506.48,5708.66 3546.48,5708.66 6020,5719 6070,5719 6211,5719 6161,5721 4338,5733 4309.87,5758 4196.9,5778.67 4338,5783.46 4309.87,5808.46 5804.31,5834 6386.69,5834 4196.32,5859.46 6850.39,5866.14 7244.09,5866.14 7637.8,5866.14 8031.5,5866.14 8425.2,5866.14 8818.9,5866.14 2968.53,5878.46 3189.03,5878.46
DISPLAYPORT_PL_SNK_AUX_N: C34.2 MC3.99 R179.1 | length 6057.9
  L1-TOP w3.3: R179.1@7476.69,1181 v1(7510.92,1181)
  L1-TOP w5.25: v1@2431.77,3045.28 2434.07,3045.28 2440.35,3039 2474.43,3039 MC3.99@2476.77,3041.34
  L3-SIG1 w3.15: v1(4721,2779.84) 4732.25,2768.59 5021.41,2768.59 6225,1565 6929.27,1565 6943.27,1579 7054,1579 7347,1286 7516.73,1286 7548,1254.73 7548,1205.77 7536.73,1194.5 7524.42,1194.5 v1(7510.92,1181)
  L10-BOT w3.3: v1@2431.77,3045.28 2441.05,3036 2547.73,3036 2560.72,3023 2742.73,3023 2769.73,2996 2792.73,2996 2813.36,2975.36 3160.64,2975.36 3367.41,2768.59 4709.75,2768.59 v1(4721,2779.84)
  other v1: 2431.77,3046.28
DISPLAYPORT_PL_SNK_AUX_N_C: C34.1 R25.2 U6.26 | length 262.6
  L1-TOP w3.3: C34.1@7551.08,1181 7564.58,1194.5 7575.19,1194.5 R25.2@7587,1182.68 7598.81,1194.5 7607,1194.5 7630,1171.5 7630,1162.27 7663.77,1128.5 7760.76,1128.5 U6.26@7764.13,1125.13
DISPLAYPORT_PL_SNK_AUX_P: C33.2 MC3.97 R178.2 | length 6049.5
  L1-TOP w3.3: R178.2@7476.69,1217 v1(7510.92,1217)
  L1-TOP w5.25: v1@2431.77,3017.72 2434.07,3017.72 2440.35,3024 2474.43,3024 MC3.97@2476.77,3021.65
  L3-SIG1 w3.15: v1(4721,2748.35) 4732.25,2759.59 5017.68,2759.59 6221.27,1556 6933,1556 6947,1570 7050.27,1570 7343.27,1277 7413,1277 7430.73,1277 7433.15,1274.58 7433.15,1265.88 7435.57,1263.46 7446.88,1263.46 7449.3,1265.88 7449.3,1274.58 7451.72,1277 7455.91,1277 7513,1277 7539,1251 7539,1209.5 7533,1203.5 7524.42,1203.5 v1(7510.92,1217)
  L10-BOT w3.3: v1@2431.77,3017.72 2441.05,3027 2544,3027 2557,3014 2739,3014 2766,2987 2789,2987 2807,2969 2809.64,2966.36 3156.91,2966.36 3363.68,2759.59 4709.75,2759.59 v1(4721,2748.35)
  other v1: 2431.77,3016.62
DISPLAYPORT_PL_SNK_AUX_P_C: C33.1 R23.1 U6.25 | length 262.6
  L1-TOP w3.3: C33.1@7551.08,1217 7564.58,1203.5 7575.19,1203.5 R23.1@7587,1215.31 7598.81,1203.5 7610.73,1203.5 7639,1175.23 7639,1166 7667.5,1137.5 7760.76,1137.5 U6.25@7764.13,1140.87
DISPLAYPORT_PL_SNK_CONN_AUX_N: C36.1 J13.17 R26.2 U7.4 | length 706.1
  L1-TOP w3.3: R26.2@7670.31,1014 7669.69,1013.38 C36.1@7669.69,977.26 7656.19,963.76 7640.03,963.76 7623,946.73 7623,861.27 7687.27,797 7802.66,797 7811.63,788.03 7841.15,788.03 7855.15,774.04 7855.15,707.94 7839.96,692.75 U7.4@7839.96,670 7839.96,630.43 7814.96,605.43 J13.17@7814.96,534.65
DISPLAYPORT_PL_SNK_CONN_AUX_N_C: C36.2 U6.32 | length 107.2
  L1-TOP w3.3: C36.2@7709.85,977.26 7723.35,963.76 7730.76,963.76 7739,972 7739,989.23 7764.13,1014.36 U6.32@7764.13,1030.64
DISPLAYPORT_PL_SNK_CONN_AUX_P: C35.1 J13.15 R24.1 U7.6 | length 690.7
  L1-TOP w3.3: R24.1@7670.31,905 7670.31,940.64 C35.1@7669.69,941.26 7656.19,954.76 7643.76,954.76 7632,943 7632,865 7691,806 7806.39,806 7815.36,797.03 7844.88,797.03 7864.15,777.77 7864.15,707.94 7871.2,700.88 7879.33,692.75 U7.6@7879.33,670 7879.33,624.8 7854.33,599.8 J13.15@7854.33,534.65
DISPLAYPORT_PL_SNK_CONN_AUX_P_C: C35.2 U6.33 | length 114.7
  L1-TOP w3.3: C35.2@7709.85,941.26 7723.35,954.76 7734.49,954.76 7748,968.27 7748,985.5 7770.5,1008 U6.33@7786.77,1008
DISPLAYPORT_PL_SNK_CONN_LANE0_N: J13.12 U6.16 U7.7 | length 914.9
  L1-TOP w3.3: v1@7863.32,809 7872.6,799.72 7872.6,789.25 7881.89,779.96 7902.24,779.96 7914.2,768 7914.2,707.94 7899.02,692.75 U7.7@7899.02,670 7899.02,615.51 7913.39,601.14 J13.12@7913.39,534.65 ; U6.16@7897.01,1179.26 7900.38,1182.63 7900.38,1213.11 7927.06,1239.79 7927.06,1252.06 7922.12,1257 v1@7909,1257
  L10-BOT w3.3: v1@7863.32,809 7881.88,827.56 7881.88,831.27 7900,849.39 7900,1015.73 7906,1021.73 7906,1216.73 7927.56,1238.29 7927.56,1251.56 7922.12,1257 v1@7909,1257
  other v1: 7858.92,809 7907,1255
DISPLAYPORT_PL_SNK_CONN_LANE0_P: J13.10 U6.15 U7.9 | length 922.2
  L1-TOP w3.3: v1@7890.88,809 7881.6,799.72 7881.6,792.98 7885.62,788.96 7905.97,788.96 7923.2,771.73 7923.2,707.94 7930.26,700.88 7938.39,692.75 U7.9@7938.39,670 7938.39,614.14 7952.76,599.77 J13.10@7952.76,534.65 ; U6.15@7912.76,1179.26 7909.38,1182.63 7909.38,1209.38 7933.43,1233.43 7936.06,1236.06 7936.06,1255.79 7933.43,1258.43 7928.49,1263.36 v1@7928.49,1276.49
  L10-BOT w3.3: v1@7890.88,809 7890.88,827.54 7909,845.66 7909,1012 7915,1018 7915,1213 7933.93,1231.93 7936.56,1234.56 7936.56,1255.29 7933.93,1257.93 7928.49,1263.36 v1@7928.49,1276.49
  other v1: 7888.68,809 7930.49,1278.49
DISPLAYPORT_PL_SNK_CONN_LANE1_N: J13.9 U6.18 U7.10 | length 1170.5
  L1-TOP w3.3: U6.18@7865.51,1179.26 7868.89,1182.63 7868.89,1333.74 7909.51,1374.36 v1@7909.51,1387.49 ; v1@7946,809 7955.28,799.72 7955.28,789 7973.26,771.02 7973.26,707.94 7958.07,692.75 U7.10@7958.07,670 7958.07,611.46 7972.44,597.09 J13.9@7972.44,534.65
  L10-BOT w3.3: v1@7909.51,1387.49 7909.51,1374.36 7902.07,1366.93 7899.44,1364.29 7899.44,1337.83 7902.07,1335.2 7919.27,1318 7960.03,1318 7970.52,1307.51 7970.52,1282.25 7955.28,1267.01 7955.28,818.28 v1@7946,809
  other v1: 7948.2,809 7908.51,1388.49
DISPLAYPORT_PL_SNK_CONN_LANE1_P: J13.7 U6.17 U7.12 | length 1155.6
  L1-TOP w3.3: U6.17@7881.26,1179.26 7877.89,1182.63 7877.89,1330.01 7915.88,1368 v1@7929,1368 ; v1@7973.56,809 7964.28,799.72 7964.28,792.73 7982.26,774.75 7982.26,707.94 7989.31,700.88 7997.44,692.75 U7.12@7997.44,670 7997.44,622.09 8011.81,607.72 J13.7@8011.81,534.65
  L10-BOT w3.3: v1@7929,1368 7915.88,1368 7908.44,1360.56 7908.44,1341.56 7923,1327 7963.76,1327 7979.52,1311.24 7979.52,1278.52 7964.28,1263.28 7964.28,818.28 v1@7973.56,809
  other v1: 7977.96,809 7930,1367
DISPLAYPORT_PL_SNK_HPD: MC3.95 U4.10 | length 577.9
  L1-TOP w5: U4.10@1900.59,2997.75 2439.75,2997.75 2443.97,3001.97 MC3.95@2476.77,3001.97
DISPLAYPORT_PL_SNK_HPD_3V3: R35.2 R180.1 U4.2 | length 7558.3
  L1-TOP w5: v1(1816.76,3015.84) 1834.85,2997.75 U4.2@1849.41,2997.75 ; R180.1@7693.84,734 v1(7693.84,771)
  L3-SIG1 w5: v1(4830.92,2889.08) 4830.92,2853.1 4795.9,2818.07 4763.93,2818.07 4741,2841 4713,2841 4693.42,2821.42 4693.42,2703.58 4709,2688 4987,2688 6378,1297 6944,1297 7111,1130 7111,1036 7179,968 7179,854 7262,771 v1(7693.84,771)
  L10-BOT w5: v1(1816.76,3015.84) 1857.93,3057 1923,3057 2085,3219 4501,3219 v1(4830.92,2889.08)
DISPLAYPORT_PL_SNK_LANE0_N: C30.2 MC2.107 | length 3402.3
  L10-BOT w3.3: v1(4937.01,1665.4) 4925.76,1654.15 4925.76,1646 4944,1627.76 4944,1598.24 4952,1590.24 4952,1506 5181,1277 6219.27,1277 6277.27,1335 6984,1335 7019,1300 7107.73,1300 7301.73,1106 7415.73,1106 7468,1053.73 7468,981 7492,957 7722,957 7789.27,889.73 7789.27,864.68 v1(7802.77,851.18)
DISPLAYPORT_PL_SNK_LANE0_N_C: C30.1 U6.35 | length 134.3
  L1-TOP w3.3: C30.1@7802.77,891.34 7789.27,904.84 7789.27,942.85 7814.89,968.47 7814.89,1004.63 U6.35@7818.27,1008
DISPLAYPORT_PL_SNK_LANE0_P: C28.2 MC2.105 | length 3402.3
  L10-BOT w3.3: v1(4905.51,1665.4) 4916.76,1654.15 4916.76,1642.27 4935,1624.03 4935,1594.51 4943,1586.51 4943,1502.27 5165.74,1279.53 5177.27,1268 6223,1268 6234.53,1279.53 6281,1326 6980.27,1326 7015.27,1291 7104,1291 7298,1097 7412,1097 7459,1050 7459,977.27 7488.27,948 7718.27,948 7780.27,886 7780.27,864.68 v1(7766.77,851.18)
DISPLAYPORT_PL_SNK_LANE0_P_C: C28.1 U6.34 | length 134.3
  L1-TOP w3.3: C28.1@7766.77,891.34 7780.27,904.84 7780.27,946.57 7805.89,972.2 7805.89,1004.63 U6.34@7802.52,1008
DISPLAYPORT_PL_SNK_LANE1_N: C32.2 MC2.111 | length 3313.7
  L10-BOT w3.3: v1(4996.06,1609.4) 4984.81,1598.15 4984.81,1578.96 5007.26,1556.52 5065.21,1556.52 5291.73,1330 6202.27,1330 6251.27,1379 7009.69,1379 7043.35,1345.35 7154.65,1345.35 7350,1150 7437,1150 7470.86,1116.14 7568.86,1116.14 7571.5,1113.5 7691,994 7774,994 7804,964 7840.73,964 7862.27,942.46 7862.27,864.68 v1(7875.77,851.18)
DISPLAYPORT_PL_SNK_LANE1_N_C: C32.1 U6.38 | length 123.7
  L1-TOP w3.3: U6.38@7865.51,1008 7862.14,1004.63 7862.14,904.97 C32.1@7875.77,891.34
DISPLAYPORT_PL_SNK_LANE1_P: C31.2 MC2.109 | length 3313.7
  L10-BOT w3.3: v1(4964.57,1609.4) 4975.81,1598.15 4975.81,1575.24 5003.53,1547.52 5061.48,1547.52 5270.42,1338.58 5288,1321 6206,1321 6223.58,1338.58 6255,1370 7005.96,1370 7039.62,1336.35 7150.93,1336.35 7346.27,1141 7433.27,1141 7467.14,1107.14 7565.14,1107.14 7687.27,985 7770.27,985 7800.27,955 7837,955 7853.27,938.73 7853.27,864.68 v1(7839.77,851.18)
DISPLAYPORT_PL_SNK_LANE1_P_C: C31.1 U6.37 | length 123.6
  L1-TOP w3.3: C31.1@7839.77,891.34 7853.14,904.7 7853.14,1004.63 U6.37@7849.76,1008
DISPLAYPORT_PL_SRC_AUX_N: C173.1 J21.17 R173.1 U26.4 | length 588.7
  L1-TOP w3.3: C173.1@6693.08,828 6706.42,841.34 6717.34,841.34 R173.1@6729,829.69 6740.66,841.34 6759.66,841.34 6809,792 6913.45,792 6933.96,771.5 6933.96,704.7 6918.77,689.51 U26.4@6918.77,664.85 6918.77,641.14 6890.63,613 6849.53,613 6830.71,594.18 J21.17@6830.71,534.65
DISPLAYPORT_PL_SRC_AUX_N_C: C173.2 MC3.89 R172.1 | length 5282.4
  L1-TOP w3.3: v1(6619.69,828) 6633.19,841.5 6639.42,841.5 C173.2@6652.92,828
  L1-TOP w5.25: v1@2431.77,2946.85 2434.07,2946.85 2440.35,2940.57 2474.43,2940.57 MC3.89@2476.77,2942.91
  L3-SIG1 w3.15: v1(4721,2622.36) 4732.25,2611.11 4960.61,2611.11 6662,909.73 6662,858.77 6644.73,841.5 6633.19,841.5 v1(6619.69,828)
  L10-BOT w3.3: v1@2431.77,2946.85 2441.05,2937.57 2647.16,2937.57 2745.73,2839 3059.73,2839 3287.61,2611.11 4709.75,2611.11 v1(4721,2622.36)
  other v1: 2431.77,2947.85
DISPLAYPORT_PL_SRC_AUX_P: C172.1 J21.15 R171.2 U26.6 | length 614.4
  L1-TOP w3.3: C172.1@6693.08,864 6706.74,850.34 6717.34,850.34 R171.2@6729,862 6740.66,850.34 6763.39,850.34 6769.27,844.45 6771.91,841.82 6812.73,801 6917.18,801 6942.96,775.23 6942.96,704.75 6958.14,689.56 U26.6@6958.14,664.85 6958.14,623.28 6938.86,604 6879.53,604 6870.08,594.55 J21.15@6870.08,534.65
DISPLAYPORT_PL_SRC_AUX_P_C: C172.2 MC3.87 R170.2 | length 5252.5
  L1-TOP w3.3: v1(6619.69,864) 6633.19,850.5 6639.42,850.5 C172.2@6652.92,864
  L1-TOP w5.25: v1@2431.77,2919.29 2434.07,2919.29 2440.35,2925.57 2474.43,2925.57 MC3.87@2476.77,2923.23
  L3-SIG1 w3.15: v1(4721,2590.87) 4732.25,2602.11 4956.89,2602.11 6653,906 6653,862.5 6641,850.5 6633.19,850.5 v1(6619.69,864)
  L10-BOT w3.3: v1@2431.77,2919.29 2441.05,2928.57 2643.43,2928.57 2742,2830 3056,2830 3283.89,2602.11 4709.75,2602.11 v1(4721,2590.87)
  other v1: 2431.77,2918.19
DISPLAYPORT_PL_SRC_CONN_LANE0_N: C206.1 J21.3 U26.10 | length 352.4
  L1-TOP w3.3: C206.1@7044.83,820.36 7058.33,806.86 7058.33,766.05 7051.93,759.66 7051.93,704.3 7036.88,689.25 U26.10@7036.88,664.85 7036.88,624.65 7047.56,613.97 7087.56,613.97 7106.3,595.23 J21.3@7106.3,534.65
DISPLAYPORT_PL_SRC_CONN_LANE0_N_C: C206.2 U25.30 | length 98.6
  L1-TOP w3.3: U25.30@7010.2,917.44 7010.2,906.17 7015.54,900.83 7015.54,892.27 7025.81,882 7053.33,882 7058.33,877 7058.33,874.02 C206.2@7044.83,860.52
DISPLAYPORT_PL_SRC_CONN_LANE0_P: C203.1 J21.1 U26.12 | length 349
  L1-TOP w3.3: C203.1@7080.83,820.36 7067.33,806.86 7067.33,762.33 7060.93,755.93 7060.93,704.69 7076.25,689.36 U26.12@7076.25,664.85 7076.25,641.28 7106.53,611 7140.53,611 7145.67,605.86 J21.1@7145.67,534.65
DISPLAYPORT_PL_SRC_CONN_LANE0_P_C: C203.2 U25.31 | length 98.6
  L1-TOP w3.3: U25.31@7029.88,917.44 7029.88,905.5 7024.54,900.16 7024.54,896 7029.54,891 7057.05,891 7067.33,880.73 7067.33,874.02 C203.2@7080.83,860.52
DISPLAYPORT_PL_SRC_CONN_LANE1_N: C210.1 J21.6 U26.7 | length 367.3
  L1-TOP w3.3: C210.1@6936.83,829.36 6950.33,815.86 6950.33,805.94 6993.01,763.26 6993.01,704.24 6977.83,689.06 U26.7@6977.83,664.85 6977.83,622.7 6992.52,608 7016.86,608 7047.24,577.62 J21.6@7047.24,534.65
DISPLAYPORT_PL_SRC_CONN_LANE1_N_C: C210.2 U25.27 | length 58.3
  L1-TOP w3.3: C210.2@6936.83,869.52 6956.48,889.18 6956.48,900.75 6951.14,906.1 U25.27@6951.14,917.44
DISPLAYPORT_PL_SRC_CONN_LANE1_P: C208.1 J21.4 U26.9 | length 374.7
  L1-TOP w3.3: C208.1@6972.83,829.36 6959.33,815.86 6959.33,809.67 7002.01,766.99 7002.01,704.61 7017.2,689.43 U26.9@7017.2,664.85 7017.2,626.33 7038.53,605 7075.53,605 7086.61,593.91 J21.4@7086.61,534.65
DISPLAYPORT_PL_SRC_CONN_LANE1_P_C: C208.2 U25.28 | length 53.2
  L1-TOP w3.3: U25.28@6970.83,917.44 6970.83,906.06 6965.48,900.72 6965.48,876.86 C208.2@6972.83,869.52
DISPLAYPORT_PL_SRC_HPD: MC3.93 U4.9 | length 576.3
  L1-TOP w5: U4.9@1900.59,2982 1900.87,2982.28 MC3.93@2476.77,2982.28
DISPLAYPORT_PL_SRC_HPD_3V3: R166.2 R182.1 U4.3 | length 6649.9
  L1-TOP w5: v1(1816.76,2982.08) 1816.84,2982 U4.3@1849.41,2982 ; R182.1@6773.84,720 v1(6773.84,756)
  L3-SIG1 w5: v1(4806,2863) 4778,2891 4704,2891 4653.44,2840.44 4653.44,2554.69 4727.12,2481 4810,2481 6452.5,838.5 6452.5,818.5 6531,740 6757.84,740 v1(6773.84,756)
  L10-BOT w5: v1(1816.76,2982.08) 1899.08,2982.08 2118,3201 2785,3201 2811,3175 4494,3175 v1(4806,2863)
DISPLAYPORT_PL_SRC_LANE0_N: C205.2 MC2.108 | length 2434.5
  L10-BOT w3.3: v1(4937.01,1422.09) 4925.76,1410.85 4925.76,1321.97 5077.31,1170.42 6568.03,1170.42 6572.86,1170.42 6575.3,1172.86 6575.3,1181.51 6577.75,1183.96 6589.16,1183.96 6591.6,1181.51 6591.6,1172.86 6594.05,1170.42 6612,1170.42 6635.58,1170.42 6682,1124 6699,1107 6998,1107 7058.33,1167.33 7058.33,1210.02 v1(7044.83,1223.52)
DISPLAYPORT_PL_SRC_LANE0_N_C: C205.1 U25.2 | length 110.2
  L1-TOP w3.3: U25.2@7010.2,1112.32 7010.2,1123.34 7015.54,1128.68 7015.54,1136.73 7024.81,1146 7048,1146 7058.33,1156.33 7058.33,1169.86 C205.1@7044.83,1183.36
DISPLAYPORT_PL_SRC_LANE0_P: C202.2 MC2.106 | length 2443
  L10-BOT w3.3: v1(4905.51,1422.09) 4916.76,1410.85 4916.76,1318.24 5073.58,1161.42 6631.85,1161.42 6695.27,1098 7001.73,1098 7067.33,1163.6 7067.33,1210.02 v1(7080.83,1223.52)
DISPLAYPORT_PL_SRC_LANE0_P_C: C202.1 U25.1 | length 110.2
  L1-TOP w3.3: U25.1@7029.88,1112.32 7029.88,1123.18 7024.54,1128.52 7024.54,1133 7028.54,1137 7051.73,1137 7067.33,1152.6 7067.33,1169.86 C202.1@7080.83,1183.36
DISPLAYPORT_PL_SRC_LANE1_N: C209.2 MC2.112 | length 2188.3
  L10-BOT w3.3: v1(4996.06,1366.09) 4984.81,1354.85 4984.81,1329.91 5089.73,1225 6325.27,1225 6381.27,1281 6674,1281 6689.86,1281 6692.3,1283.45 6692.3,1292.1 6694.75,1294.54 6706.16,1294.54 6708.6,1292.1 6708.6,1283.45 6711.05,1281 6729,1281 6771.73,1281 6831,1221.73 6831,1186 6846,1171 6937.33,1171 6950.33,1184 6950.33,1187.02 v1(6936.83,1200.52)
DISPLAYPORT_PL_SRC_LANE1_N_C: C209.1 U25.5 | length 58.4
  L1-TOP w3.3: C209.1@6936.83,1160.36 6956.48,1140.7 6956.48,1129.07 6951.14,1123.72 U25.5@6951.14,1112.32
DISPLAYPORT_PL_SRC_LANE1_P: C207.2 MC2.110 | length 2196.8
  L10-BOT w3.3: v1(4964.57,1366.09) 4975.81,1354.85 4975.81,1326.19 5081.53,1220.47 5086,1216 6329,1216 6333.47,1220.47 6385,1272 6768,1272 6822,1218 6822,1182.27 6842.27,1162 6941.05,1162 6959.33,1180.27 6959.33,1187.02 v1(6972.83,1200.52)
DISPLAYPORT_PL_SRC_LANE1_P_C: C207.1 U25.4 | length 53.3
  L1-TOP w3.3: U25.4@6970.83,1112.32 6970.83,1123.44 6965.48,1128.79 6965.48,1153.02 C207.1@6972.83,1160.36
DISPLAYPORT_PL_SRC_PWD_B: MC3.91 U4.8 | length 577.7
  L1-TOP w5: U4.8@1900.59,2966.25 2440.75,2966.25 2444.4,2962.6 MC3.91@2476.77,2962.6
DISPLAYPORT_PL_SRC_PWD_B_3V3: U4.4 U25.37 | length 6912.5
  L1-TOP w5: v1(1816.76,2947.58) 1835.43,2966.25 U4.4@1849.41,2966.25
  L3-SIG1 w5: v1(4780.43,2840.57) 4756,2865 4709,2865 4672.48,2828.48 4672.48,2567.52 4729,2511 4811,2511 6479.5,842.5 6479.5,823.5 6540,763 6626,763 6823,960 7000,960 7014,974 7014,1032.83 v1(7035.43,1054.25)
  L10-BOT w5: v1(1816.76,2947.58) 1827.18,2958 1935,2958 2158,3181 2716,3181 2758,3139 4482,3139 v1(4780.43,2840.57)
DISPLAYPORT_PL_SRC_VCC: C191.2 C192.2 C193.2 C194.2 C195.2 C196.2 C197.2 C198.2 C199.2 C200.2 C201.2 R160.2 U25.3 U25.6 U25.7 U25.10 U25.13 U25.19 U25.22 U25.25 U25.26 U25.29 U25.32 U25.38 | length 452.6
  L1-TOP w11: v1(6911.77,894.44) 6931.46,894.44 U25.26@6931.46,917.44 ; v1(6911.77,1135.32) 6931.46,1135.32 U25.6@6931.46,1112.32 ; U25.29@6990.51,917.44 6990.51,892.24 v1(7001.54,881.21) ; U25.3@6990.51,1112.32 6990.51,1136.82 v1(7000.18,1146.48)
  L1-TOP w18: C193.2@6739.91,955.44 6740.29,955.83 v1(6761.8,955.83) ; C194.2@6739.91,1074.44 6740.41,1073.94 v1(6761.8,1073.94) ; v1(6852.72,894.44) 6852.83,894.44 C200.2@6852.83,873.52 ; v1(6852.72,1135.32) 6852.83,1135.32 C195.2@6852.83,1156.36 ; C199.2@6900.83,873.52 6911.77,884.46 v1(6911.77,894.44) ; C196.2@6900.83,1156.36 6911.77,1145.42 v1(6911.77,1135.32) ; v1(7000.18,1146.48) 7009,1155.3 C197.2@7009,1164.92 ; v1(7001.54,881.21) 7009,873.75 C201.2@7009,860.08 ; v1(7081.43,955.83) 7102.36,955.83 C198.2@7102.75,955.44 ; v1(7081.43,1073.94) 7102.24,1073.94 C192.2@7102.75,1074.44
  L1-TOP w32: C191.2@6801.43,1172.44 6802.83,1173.83 R160.2@6802.83,1233.44
  other v1: 6801.43,1154.72 6801.43,1190.16
DISPLAYPORT_PS_SRC_AUX_N: C171.1 J20.17 R167.1 U24.4 | length 422.1
  L1-TOP w3.3: J20.17@1633.86,534.65 1633.86,591.19 1664.67,622 1707.53,622 1727.04,641.51 U24.4@1727.04,665 1727.04,687.75 1742.22,702.94 1742.22,768.58 1712.53,798.27 1712.53,809 R167.1@1699.53,822 1712.53,835 1712.53,843.92 C171.1@1698.53,857.92
DISPLAYPORT_PS_SRC_AUX_N_C: C171.2 MC3.153 R158.1 | length 3896.1
  L1-TOP w3.3: C171.2@1698.53,898.08 1712.53,912.08 1712.53,922.69 v1(1700.21,935) ; v1@2401.77,3773.62 2411.05,3764.34 2448.88,3764.34 2454.22,3769.69 MC3.153@2476.77,3769.69
  L3-SIG1 w3.15: v1(1700.21,935) 1712.53,947.32 1712.53,963.73 1839.8,1091 1880.27,1091 2501.27,1712 2624.2,1712 2823.11,1910.9 2823.11,2755.83 2851,2783.73 2871.03,2803.76 2871.03,3148.41 2677.44,3342 2583.27,3342 2465,3460.27 2455.92,3469.35 2455.92,3564.08 2443,3577 2400.4,3577 2338.49,3638.91 2338.49,3746.22 2356.61,3764.34 2392.49,3764.34 v1@2401.77,3773.62
  other v1: 2401.77,3774.62
DISPLAYPORT_PS_SRC_AUX_P: C170.1 J20.15 R154.2 U24.6 | length 436.9
  L1-TOP w3.3: J20.15@1673.23,534.65 1673.23,597.7 1683.53,608 1751.53,608 1766.41,622.88 U24.6@1766.41,665 1766.41,687.75 1758.28,695.88 1751.22,702.94 1751.22,772.3 1721.53,802 1721.53,809 R154.2@1734.53,822 1721.53,835 1721.53,843.92 C170.1@1735.53,857.92
DISPLAYPORT_PS_SRC_AUX_P_C: C170.2 MC3.151 R153.2 | length 3881.2
  L1-TOP w3.3: v1(1733.84,935) 1721.53,922.68 1721.53,912.08 C170.2@1735.53,898.08 ; v1@2401.77,3746.06 2411.05,3755.34 2448.69,3755.34 2454.03,3750 MC3.151@2476.77,3750
  L3-SIG1 w3.15: v1(1733.84,935) 1721.53,947.31 1721.53,960 1843.53,1082 1884,1082 2505,1703 2627.93,1703 2832.11,1907.17 2832.11,2752.11 2880.03,2800.03 2880.03,3152.14 2681.17,3351 2587,3351 2464.92,3473.08 2464.92,3567.81 2446.73,3586 2404.13,3586 2347.49,3642.64 2347.49,3742.49 2360.34,3755.34 2392.49,3755.34 v1@2401.77,3746.06
  other v1: 2401.77,3744.96
DISPLAYPORT_PS_SRC_CONN_LANE0_N: C185.1 J20.3 U24.10 | length 390.4
  L1-TOP w3.3: C185.1@1877.09,858.92 1890.59,845.42 1890.59,834.99 1860.33,804.73 1860.33,702.94 1845.15,687.75 U24.10@1845.15,665 1845.15,626.38 1857.45,614.08 1883.24,614.08 1909.45,587.87 J20.3@1909.45,534.65
DISPLAYPORT_PS_SRC_CONN_LANE0_P: C182.1 J20.1 U24.12 | length 385.8
  L1-TOP w3.3: C182.1@1913.09,858.92 1899.59,845.42 1899.59,831.26 1869.33,801 1869.33,702.94 1876.39,695.88 1884.52,687.75 U24.12@1884.52,665 1884.52,642.13 1910.65,616 1928.53,616 1948.82,595.71 J20.1@1948.82,534.65
DISPLAYPORT_PS_SRC_CONN_LANE1_N: C189.1 J20.6 U24.7 | length 388.1
  L1-TOP w3.3: C189.1@1805.09,858.92 1818.59,845.42 1818.59,822.04 1801.28,804.73 1801.28,702.94 1786.09,687.75 U24.7@1786.09,665 1786.09,620.43 1799.53,607 1830.53,607 1850.39,587.13 J20.6@1850.39,534.65
DISPLAYPORT_PS_SRC_CONN_LANE1_P: C187.1 J20.4 U24.9 | length 385.6
  L1-TOP w3.3: C187.1@1841.09,858.92 1827.59,845.42 1827.59,818.32 1810.28,801 1810.28,702.94 1825.46,687.75 U24.9@1825.46,665 1825.46,630.42 1851.96,603.93 1878.6,603.93 1889.76,592.76 J20.4@1889.76,534.65
DISPLAYPORT_PS_SRC_HPD: MC3.157 U5.10 | length 1562.4
  L1-TOP w5: MC3.157@2476.77,3809.06 2358.06,3809.06 2328,3779 2328,3484 2400,3412 2495.05,3412 2575.05,3492 2628,3492 2714,3406 3292,3406 3309.25,3388.75 U5.10@3309.25,3369.59
DISPLAYPORT_PS_SRC_HPD_3V3: R159.2 R181.1 U5.2 | length 3727.7
  L1-TOP w5: R159.2@1624.53,897.68 v1(1661.53,897.69) ; v1(2865,3195) 3200.4,3195 3309.25,3303.85 U5.2@3309.25,3318.41
  L3-SIG1 w5: v1(1661.53,897.69) 1688.21,871 2215,871 2779,1435 2779,1781 2900,1902 2900,3160 v1(2865,3195)
DISPLAYPORT_PS_SRC_LANE0_N: C185.2 MC2.28 | length 1806
  L10-BOT w3.3: v1(1877.09,899.08) 1890.59,885.58 1890.59,873.27 1912.87,851 2805.73,851 2923,968.27 2923,1066 3006,1149 3031,1174 3262,1405 3345.11,1405 v1(3362.2,1422.09)
DISPLAYPORT_PS_SRC_LANE0_P: C182.2 MC2.26 | length 1820
  L10-BOT w3.3: v1(1913.09,899.08) 1899.59,885.58 1899.59,877 1916.59,860 1924,860 1927.86,860 1930.3,862.45 1930.3,871.1 1932.75,873.54 1944.16,873.54 1946.6,871.1 1946.6,862.45 1949.05,860 1967,860 2802,860 2914,972 2914,1069.73 3176.32,1332.04 3183.41,1339.14 3183.41,1342.59 3177.29,1348.71 3177.29,1352.17 3185.36,1360.24 3188.82,1360.24 3194.93,1354.12 3198.39,1354.12 3206.46,1362.19 3206.46,1365.65 3200.34,1371.76 3200.34,1375.22 3208.41,1383.29 3211.87,1383.29 3217.99,1377.17 3221.44,1377.17 3234.14,1389.86 3258.27,1414 3322.61,1414 v1(3330.71,1422.09)
DISPLAYPORT_PS_SRC_LANE1_N: C189.2 MC2.24 | length 1858.7
  L10-BOT w3.3: v1(1805.09,899.08) 1818.59,885.58 1818.59,872.27 1886.87,804 2878.73,804 3291.9,1217.17 3291.9,1354.85 v1(3303.15,1366.09)
DISPLAYPORT_PS_SRC_LANE1_P: C187.2 MC2.22 | length 1855.6
  L10-BOT w3.3: v1(1841.09,899.08) 1827.59,885.58 1827.59,876 1890.59,813 2006,813 2015.52,813 2017.96,815.45 2017.96,820.11 2020.41,822.56 2031.82,822.56 2034.26,820.11 2034.26,815.45 2036.71,813 2048.12,813 2050.56,815.45 2050.56,820.11 2053.01,822.56 2064.42,822.56 2066.86,820.11 2066.86,815.45 2069.31,813 2087.26,813 2875,813 3282.9,1220.9 3282.9,1354.85 v1(3271.65,1366.09)
ETH_TXRX_A_N: J17.10 U16.3 | length 1053.3
  L1-TOP w3.3: U16.3@4395.76,5016.38 4401.1,5011.04 4503.96,5011.04 4505.14,5011.04 4547.33,4968.85 4772.15,4968.85 4837.52,4903.48 4898.72,4903.48 v1@4908,4912.76
  L10-BOT w3.3: v1@4908,4912.76 4917.28,4903.48 5067.48,4903.48 5130,4966 5131.17,4967.17 5131.17,4972.91 5128.42,4975.65 5128.42,4981.39 5137.04,4990.01 5142.78,4990.01 5145.52,4987.26 5151.26,4987.26 5159.88,4995.88 5159.88,5001.62 5158.99,5002.5 5158.99,5008.24 5167.6,5016.85 5173.35,5016.85 5174.23,5015.97 5179.97,5015.97 5195.5,5031.5 5241.5,5077.5 5241.5,5097 5235.9,5102.6 J17.10@5206,5102.6
  other v1: 4908,4910.56
ETH_TXRX_A_P: J17.11 U16.2 | length 1044.5
  L1-TOP w3.3: U16.2@4395.76,4996.7 4401.1,5002.04 4501.42,5002.04 4543.6,4959.85 4768.42,4959.85 4833.79,4894.48 4860.27,4894.48 4898.72,4894.48 v1@4908,4885.2
  L10-BOT w3.3: v1@4908,4885.2 4917.28,4894.48 5071.21,4894.48 5250.5,5073.77 5250.5,5097 5256.1,5102.6 J17.11@5286,5102.6
  other v1: 4908,4880.8
ETH_TXRX_B_N: J17.5 U16.6 | length 1049.2
  L1-TOP w3.3: U16.6@4395.76,5075.44 4401.1,5070.1 4488.9,5070.1 4509.86,5049.14 ; 4510,5049 4533,5026 4548,5026 4575.69,4998.31 4796.69,4998.31 4821,4974 4845.76,4974 v1(4862.76,4991)
  L10-BOT w3.3: v1(4862.76,4991) 4887.76,4966 5049.73,4966 5154,5070.27 5154,5113.27 5210.5,5169.77 5210.5,5198 5215.1,5202.6 J17.5@5246,5202.6
ETH_TXRX_B_P: J17.4 U16.5 | length 1049
  L1-TOP w3.3: U16.5@4395.76,5055.75 4401.1,5061.1 4485.18,5061.1 4529.27,5017 4544.27,5017 4571.96,4989.31 4792.96,4989.31 4817.27,4965 4866.52,4965 v1(4892.52,4991)
  L10-BOT w3.3: v1(4892.52,4991) 4908.52,4975 4979,4975 4980.65,4975 4984.71,4979.06 4984.71,4982.94 4988.77,4987 5000.95,4987 5005.01,4982.94 5005.01,4979.06 5009.07,4975 5029,4975 5046,4975 5145,5074 5145,5117 5201.5,5173.5 5201.5,5198 5196.9,5202.6 J17.4@5166,5202.6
